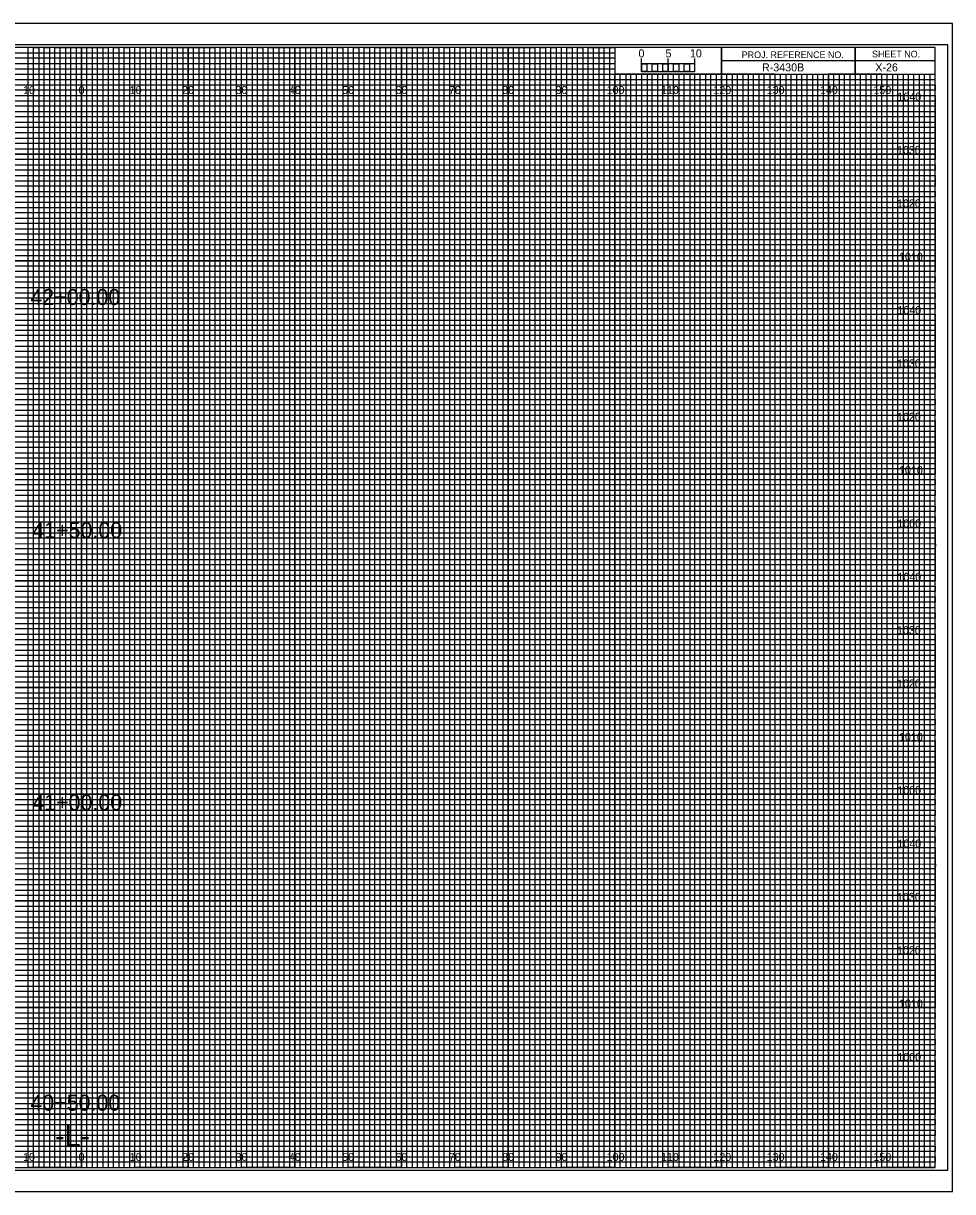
# Model space of a CAD drawing. Extents: x -13 to 323, y 5276 to 5494.
# Drawn here: x 149.1 to 323.3, y 5275.5 to 5494.5 of the extents above; entities that cross this region are included whole.
import ezdxf

# ---------------------------------------------------------------- set-up
doc = ezdxf.new("R2010")
doc.units = 0
for name, color, linetype in [('Prop XS Alignment Label', 7, 'Continuous'), ('Prop XS Bar Scale Labels', 7, 'Continuous'), ('Prop XS Elevation Labels', 7, 'Continuous'), ('Prop XS Offset Labels', 7, 'Continuous'), ('Prop XS Project Number', 7, 'Continuous'), ('Prop XS Sheet Number', 7, 'Continuous'), ('Prop XS Station Labels', 7, 'Continuous'), ('Sheet Cross Section CELL', 7, 'Continuous'), ('Sheet Cross Section Grid Major CELL', 7, 'Continuous'), ('Sheet Cross Section Grid Middle CELL', 7, 'Continuous'), ('Sheet Cross Section Grid Minor 1 CELL', 7, 'Continuous'), ('Sheet Cross Section Grid Minor 2 CELL', 7, 'Continuous'), ('Sheet Cross Section Scale CELL', 7, 'Continuous'), ('Sheet Cutting Line CELL', 7, 'Continuous'), ('Sheet DOT Grid CELL', 7, 'Continuous'), ('Sheet Plot Border Inside CELL', 7, 'Continuous'), ('Sheet Plot Border Outside CELL', 7, 'Continuous')]:
    doc.layers.add(name, color=color, linetype=linetype)

msp = doc.modelspace()

# ---------------------------------------------------------------- linework, layer by layer
at = {"layer": 'Sheet Cross Section CELL'}
for p, q in [((305, 5490), (305, 5485)), ((305, 5485), (305, 5490)), ((280, 5487.5), (280, 5485)), ((320, 5487.49), (280, 5487.49)), ((280, 5485), (320, 5485))]:
    msp.add_line(p, q, dxfattribs=at)
for points in [[(320, 5490), (0, 5490), (0, 5280), (320, 5280)], [(280, 5490), (260, 5490), (260, 5485.03), (280, 5485.03)], [(320, 5490), (280, 5490), (280, 5485), (320, 5485)]]:
    msp.add_lwpolyline(points, close=True, dxfattribs=at)
at = {"layer": 'Sheet Cross Section Grid Major CELL'}
for p, q in [((150, 5490), (140, 5490)), ((150, 5280), (150, 5490)), ((170, 5490), (160, 5490)), ((160, 5490), (160, 5280)), ((170, 5280), (170, 5490)), ((190, 5490), (180, 5490)), ((180, 5490), (180, 5280)), ((190, 5280), (190, 5490)), ((210, 5490), (200, 5490)), ((200, 5490), (200, 5280)), ((210, 5280), (210, 5490)), ((230, 5490), (220, 5490)), ((220, 5490), (220, 5280)), ((230, 5280), (230, 5490)), ((250, 5490), (240, 5490)), ((240, 5490), (240, 5280)), ((250, 5280), (250, 5490)), ((260, 5490), (260, 5280)), ((270, 5280), (270, 5485)), ((290, 5485), (280, 5485)), ((280, 5485), (280, 5280)), ((290, 5280), (290, 5485)), ((310, 5485), (300, 5485)), ((300, 5485), (300, 5280)), ((310, 5280), (310, 5485)), ((160, 5280), (150, 5280)), ((180, 5280), (170, 5280)), ((200, 5280), (190, 5280)), ((220, 5280), (210, 5280)), ((240, 5280), (230, 5280)), ((260, 5280), (250, 5280)), ((280, 5280), (270, 5280)), ((300, 5280), (290, 5280)), ((320, 5280), (310, 5280)), ((320, 5280), (320, 5280))]:
    msp.add_line(p, q, dxfattribs=at)
for points in [[(0, 5480), (320, 5480), (320, 5470), (0, 5470)], [(0, 5460), (320, 5460), (320, 5450), (0, 5450)], [(0, 5440), (320, 5440), (320, 5430), (0, 5430)], [(0, 5420), (320, 5420), (320, 5410), (0, 5410)], [(0, 5400), (320, 5400), (320, 5390), (0, 5390)], [(0, 5380), (320, 5380), (320, 5370), (0, 5370)], [(0, 5360), (320, 5360), (320, 5350), (0, 5350)], [(0, 5340), (320, 5340), (320, 5330), (0, 5330)], [(0, 5320), (320, 5320), (320, 5310), (0, 5310)], [(0, 5300), (320, 5300), (320, 5290), (0, 5290)]]:
    msp.add_lwpolyline(points, dxfattribs=at)
at = {"layer": 'Sheet Cross Section Grid Middle CELL'}
for points in [[(145, 5280), (155, 5280), (155, 5490), (165, 5490), (165, 5280), (175, 5280), (175, 5490), (185, 5490), (185, 5280), (195, 5280), (195, 5490), (205, 5490), (205, 5280), (215, 5280), (215, 5490), (225, 5490), (225, 5280), (235, 5280), (235, 5490), (245, 5490), (245, 5280), (255, 5280), (255, 5490), (259.93, 5490), (260, 5490), (260, 5485), (264.99, 5485), (264.99, 5280), (275, 5280), (275, 5485), (285, 5485), (285, 5280), (295, 5280), (295, 5485), (305, 5485), (305, 5280), (315, 5280), (315, 5485)], [(0, 5485), (275, 5485)], [(0, 5465), (320, 5465), (320, 5475), (0, 5475)], [(0, 5445), (320, 5445), (320, 5455), (0, 5455)], [(0, 5425), (320, 5425), (320, 5435), (0, 5435)], [(0, 5405), (320, 5405), (320, 5415), (0, 5415)], [(0, 5385), (320, 5385), (320, 5395), (0, 5395)], [(0, 5365), (320, 5365), (320, 5375), (0, 5375)], [(0, 5345), (320, 5345), (320, 5355), (0, 5355)], [(0, 5325), (320, 5325), (320, 5335), (0, 5335)], [(0, 5305), (320, 5305), (320, 5315), (0, 5315)], [(0, 5285), (320, 5285), (320, 5295), (0, 5295)]]:
    msp.add_lwpolyline(points, dxfattribs=at)
at = {"layer": 'Sheet Cross Section Grid Minor 1 CELL'}
for p, q in [((0, 5489), (260, 5489)), ((260, 5489), (260, 5487.98)), ((260, 5487.98), (0, 5487.98)), ((0, 5487), (260, 5487)), ((260, 5487), (260, 5485.89)), ((260, 5485.89), (0, 5485.89)), ((0, 5484), (320, 5484))]:
    msp.add_line(p, q, dxfattribs=at)
for points in [[(0, 5483), (270, 5483), (320, 5483), (320, 5482), (0, 5482)], [(0, 5481), (320, 5481), (320, 5479), (0, 5479)], [(0, 5478), (320, 5478), (320, 5477), (0, 5476.98)], [(0, 5476), (320, 5476), (320, 5474), (0, 5474)], [(0, 5473), (320, 5473), (320, 5472), (0, 5472)], [(0, 5471), (320, 5471), (320, 5469), (0, 5469)], [(0, 5468), (320, 5468), (320, 5467), (0, 5467)], [(0, 5466), (320, 5466), (320, 5464), (0, 5464)], [(0, 5463), (320, 5463), (320, 5462), (0, 5462)], [(0, 5461), (320, 5461), (320, 5459), (0, 5459)], [(0, 5458), (320, 5458), (320, 5457), (0, 5457)], [(0, 5456), (320, 5456), (320, 5453.95), (320, 5453), (320, 5452), (0, 5452)], [(0, 5454), (320, 5454), (320, 5453), (0, 5453)], [(0, 5451), (320, 5451), (320, 5449), (0, 5449.03)], [(0, 5449.03), (320, 5449), (320, 5448), (0, 5448)], [(0, 5447), (320, 5447), (320, 5446), (0, 5446)], [(0, 5444), (320, 5444), (320, 5443), (0, 5443)], [(0, 5442), (320, 5442), (320, 5441), (0, 5441)], [(-0.07, 5438.89), (320, 5438.89), (320, 5437.88), (-0.07, 5437.88)], [(0, 5437), (320, 5437), (320, 5436), (0, 5436)], [(0, 5434), (320, 5434), (320, 5433), (0, 5433)], [(0, 5432), (320, 5432), (320, 5431), (0, 5431)], [(0, 5429), (320, 5429), (320, 5428), (0, 5428)], [(0, 5427), (320, 5427), (320, 5426), (0, 5426)], [(0, 5424), (320, 5424), (320, 5423), (0, 5423)], [(0, 5422), (320, 5422), (320, 5421), (0, 5421)], [(0, 5419), (320, 5419), (319.99, 5417.98), (0, 5418)], [(0, 5417), (320, 5417), (320, 5416), (0, 5416)], [(0, 5414), (320, 5414), (320, 5413), (0, 5413)], [(0, 5412), (320, 5412), (320, 5411), (0, 5411)], [(0, 5409), (320, 5409), (320, 5408), (0, 5408)], [(0, 5407), (320, 5407), (320, 5406), (0, 5406)], [(0, 5404), (320, 5404), (320, 5403), (0, 5403)], [(0, 5402), (320, 5402), (320, 5401), (0, 5401)], [(0, 5399), (320, 5399), (320, 5398), (0, 5398)], [(0, 5396.99), (320.07, 5396.91), (320, 5396), (0, 5396)], [(0, 5394), (320, 5394), (320, 5393), (0, 5393)], [(0, 5392), (320, 5392), (320, 5391), (0, 5391)], [(0, 5389), (320, 5389), (320, 5388), (0, 5388)], [(0, 5387), (320, 5387), (320, 5386), (0, 5386)], [(0, 5384), (320, 5384), (320, 5383), (0, 5383)], [(0, 5382), (320, 5382), (320, 5381), (0, 5381)], [(0, 5379), (320, 5379), (320, 5378), (0, 5378)], [(0, 5377), (320, 5377), (320, 5376), (0, 5376)], [(0, 5374), (320, 5374), (320, 5373), (0, 5373)], [(0, 5372), (320, 5372), (320, 5371), (0, 5371)], [(0, 5369), (320, 5369), (320, 5368), (0, 5368)], [(0, 5367), (320, 5367), (320, 5366), (0, 5366)], [(0, 5364), (320, 5364), (320, 5363), (0, 5363)], [(0, 5362), (320, 5362), (320, 5361), (0, 5361)], [(0, 5359), (320, 5359), (319.99, 5357.98), (0, 5358)], [(0, 5357), (320, 5357), (320, 5356), (0, 5356)], [(0, 5354), (320, 5354), (320, 5353), (0, 5353)], [(0, 5352), (320, 5352), (320, 5351), (0, 5351)], [(0, 5349), (320, 5349), (320, 5348), (0, 5348)], [(0, 5347), (320, 5347), (320, 5346), (0, 5346)], [(0, 5344), (320, 5344), (320, 5343), (0, 5343)], [(0, 5342), (320, 5342), (320, 5341), (0, 5341)], [(0, 5339), (320, 5339), (320, 5338), (0, 5338)], [(0, 5336.99), (320.07, 5336.91), (320, 5336), (0, 5336)], [(0, 5334), (320, 5334), (320, 5333), (0, 5333)], [(0, 5332), (320, 5332), (320, 5331), (0, 5331)], [(0, 5329), (320, 5329), (320, 5328), (0, 5328)], [(0, 5327), (320, 5327), (320, 5326), (0, 5326)], [(0, 5324), (320, 5324), (320, 5323), (0, 5323)], [(0, 5322), (320, 5322), (320, 5321), (0, 5321)], [(0, 5319), (320, 5319), (320, 5318), (0, 5318)], [(0, 5317), (320, 5317), (320, 5316), (0, 5316)], [(0, 5314), (320, 5314), (320, 5313), (0, 5313)], [(0, 5312), (320, 5312), (320, 5311), (0, 5311)], [(0, 5309), (320, 5309), (320, 5308), (0, 5308)], [(0, 5307), (320, 5307), (320, 5306), (0, 5306)], [(0, 5304), (320, 5304), (320, 5303), (0, 5303)], [(0, 5302), (320, 5302), (320, 5301), (0, 5301)], [(0, 5299), (320, 5299), (320, 5298), (0, 5298)], [(0, 5297), (320, 5297), (320, 5296), (0, 5296)], [(0, 5294), (320, 5294), (320, 5293), (0, 5293)], [(0, 5292), (320, 5292), (320, 5291), (0, 5291)], [(0, 5289), (320, 5289), (320, 5288), (0, 5288)], [(0, 5287), (320, 5287), (320, 5286), (0, 5286)], [(0, 5284), (320, 5284), (320, 5283), (0, 5283)], [(0, 5282), (320, 5282), (320, 5281), (0, 5281)]]:
    msp.add_lwpolyline(points, dxfattribs=at)
at = {"layer": 'Sheet Cross Section Grid Minor 2 CELL'}
for p, q in [((267, 5485), (266.01, 5485)), ((266.01, 5485), (266.01, 5280)), ((267, 5280), (267, 5485)), ((269, 5485), (268, 5485)), ((268, 5485), (268, 5280)), ((269, 5280), (269, 5485)), ((266.01, 5280), (265, 5280)), ((268, 5280), (267, 5280))]:
    msp.add_line(p, q, dxfattribs=at)
for points in [[(150, 5280), (151, 5280), (151, 5490), (152, 5490), (152, 5280)], [(152, 5280), (153, 5280), (153, 5490), (154, 5490), (154, 5280)], [(155, 5280), (156, 5280), (156, 5490), (157, 5490), (157, 5280)], [(157, 5280), (158, 5280), (158, 5490), (159, 5490), (159, 5280)], [(160, 5280), (161, 5280), (161, 5490), (162, 5490), (162, 5280)], [(162, 5280), (163, 5280), (163, 5490), (164, 5490), (164, 5280)], [(165, 5280), (166, 5280), (166, 5490), (167, 5490), (167, 5280)], [(167, 5280), (168, 5280), (168, 5490), (169, 5490), (169, 5280)], [(170, 5280), (171, 5280), (171, 5490), (172, 5490), (172, 5280)], [(172, 5280), (173, 5280), (173, 5490), (174, 5490), (174, 5280)], [(175, 5280), (176, 5280), (176, 5490), (177, 5490), (177, 5280)], [(177, 5280), (178, 5280), (178, 5490), (179, 5490), (179, 5280)], [(180, 5280), (181, 5280), (181, 5490), (182, 5490), (182, 5280)], [(182, 5280), (183, 5280), (183, 5490), (184, 5490), (184, 5280)], [(185, 5280), (186, 5280), (186, 5490), (187, 5490), (187, 5280)], [(187, 5280), (188, 5280), (188, 5490), (189, 5490), (189, 5280)], [(190, 5280), (191, 5280), (191, 5490), (192, 5490), (192, 5280)], [(192, 5280), (193, 5280), (193, 5490), (194, 5490), (194, 5280)], [(195, 5280), (196, 5280), (196, 5490), (197, 5490), (197, 5280)], [(197, 5280), (198, 5280), (198, 5490), (199, 5490), (199, 5280)], [(200, 5280), (201, 5280), (201, 5490), (202, 5490), (202, 5280)], [(202, 5280), (203, 5280), (203, 5490), (204, 5490), (204, 5280)], [(205, 5280), (206, 5280), (206, 5490), (207, 5490), (207, 5280)], [(207, 5280), (208, 5280), (208, 5490), (209, 5490), (209, 5280)], [(210, 5280), (211, 5280), (211, 5490), (212, 5490), (212, 5280)], [(212, 5280), (213, 5280), (213, 5490), (214, 5490), (214, 5280)], [(215, 5280), (216, 5280), (216, 5490), (217, 5490), (217, 5280)], [(217, 5280), (218, 5280), (218, 5490), (219, 5490), (219, 5280)], [(220, 5280), (221, 5280), (221, 5490), (222, 5490), (222, 5280)], [(222, 5280), (223, 5280), (223, 5490), (224, 5490), (224, 5280)], [(225, 5280), (226, 5280), (226, 5490), (227, 5490), (227, 5280)], [(227, 5280), (228, 5280), (228, 5490), (229, 5490), (229, 5280)], [(230, 5280), (231, 5280), (231, 5490), (232, 5490), (232, 5280)], [(232, 5280), (233, 5280), (233, 5490), (234, 5490), (234, 5280)], [(235, 5280), (236, 5280), (236, 5490), (237, 5490), (237, 5280)], [(237, 5280), (238, 5280), (238, 5490), (239, 5490), (239, 5280)], [(240, 5280), (241, 5280), (241, 5490), (242, 5490), (242, 5280)], [(242, 5280), (243, 5280), (243, 5490), (244, 5490), (244, 5280)], [(245, 5280), (246, 5280), (246, 5490), (247, 5490), (247, 5280)], [(247, 5280), (248, 5280), (248, 5490), (249, 5490), (249, 5280)], [(250, 5280), (251, 5280), (251, 5490), (252, 5490), (252, 5280)], [(252, 5280), (253, 5280), (253, 5490), (254, 5490), (254, 5280)], [(255, 5280), (256, 5280), (256, 5490), (257, 5490), (257, 5280)], [(257, 5280), (258, 5280), (258, 5490), (259, 5490), (259, 5280)], [(260, 5280), (261, 5280), (261, 5485), (262.02, 5485), (262.02, 5280)], [(262, 5280), (263, 5280), (263, 5485), (263.99, 5485), (263.99, 5280)], [(270, 5280), (270.98, 5280), (270.98, 5485), (272, 5485), (272, 5280)], [(272, 5280), (273, 5280), (273, 5485), (274.05, 5485), (274.05, 5280)], [(275, 5280), (276, 5280), (276, 5485), (277, 5485), (277, 5280)], [(277, 5280), (278, 5280), (278, 5485), (279, 5485), (279, 5280)], [(280, 5280), (281, 5280), (281, 5485), (282, 5485), (282, 5280)], [(282, 5280), (283, 5280), (283, 5485), (284, 5485), (284, 5280)], [(285, 5280), (286, 5280), (286, 5485), (287, 5485), (287, 5280)], [(287, 5280), (288, 5280), (288, 5485), (289, 5485), (289, 5280)], [(290, 5280), (291, 5280), (291, 5485), (292, 5485), (292, 5280)], [(292, 5280), (293, 5280), (293, 5485), (294, 5485), (294, 5280)], [(295, 5280), (296, 5280), (296, 5485), (297, 5485), (297, 5280)], [(297, 5280), (298, 5280), (298, 5485), (299, 5485), (299, 5280)], [(300, 5280), (301, 5280), (301, 5485), (302, 5485), (302, 5280)], [(302, 5280), (303, 5280), (303, 5485), (304, 5485), (304, 5280)], [(305, 5280), (306, 5280), (306, 5485), (307, 5485), (307, 5280)], [(307, 5280), (308, 5280), (308, 5485), (309, 5485), (309, 5280)], [(310, 5280), (311, 5280), (311, 5485), (312, 5485), (312, 5280)], [(312, 5280), (313, 5280), (313, 5485), (314, 5485), (314, 5280)], [(315, 5280), (316, 5280), (316, 5485), (317, 5485), (317, 5280)], [(317, 5280), (318, 5280), (318, 5485), (319, 5485), (319, 5280)]]:
    msp.add_lwpolyline(points, dxfattribs=at)
at = {"layer": 'Sheet Cross Section Scale CELL'}
for p, q in [((265, 5485.49), (265, 5487.9)), ((265, 5486.9), (265, 5487.9)), ((270, 5485.49), (270, 5487.9)), ((275, 5485.49), (275, 5487.9)), ((275, 5486.9), (275, 5487.9))]:
    msp.add_line(p, q, dxfattribs=at)
for points in [[(275, 5486.9), (265, 5486.9), (265, 5485.49), (275, 5485.49)], [(265, 5486.9), (266, 5486.9), (266, 5485.49), (265, 5485.49)], [(267, 5486.9), (268, 5486.9), (268, 5485.49), (267, 5485.49)], [(269, 5486.9), (270, 5486.9), (270, 5485.49), (269, 5485.49)], [(271, 5486.9), (272, 5486.9), (272, 5485.49), (271, 5485.49)], [(273, 5486.9), (274, 5486.9), (274, 5485.49), (273, 5485.49)]]:
    msp.add_lwpolyline(points, close=True, dxfattribs=at)
at = {"layer": 'Sheet Cutting Line CELL'}
for p, q in [((323.3, 5494.5), (-13.4, 5494.5)), ((-13.4, 5275.5), (323.3, 5275.5))]:
    msp.add_line(p, q, dxfattribs=at)
at = {"layer": 'Sheet DOT Grid CELL'}
for p, q in [((150, 5280), (150, 5490)), ((160, 5280), (160, 5490)), ((170, 5280), (170, 5490)), ((180, 5280), (180, 5490)), ((190, 5280), (190, 5490)), ((200, 5280), (200, 5490)), ((210, 5280), (210, 5490)), ((220, 5280), (220, 5490)), ((230, 5280), (230, 5490)), ((240, 5280), (240, 5490)), ((250, 5280), (250, 5490)), ((260, 5280), (260, 5484.69)), ((270, 5280), (270, 5484.69)), ((280, 5280), (280, 5484.69)), ((290, 5280), (290, 5484.69)), ((300, 5280), (300, 5484.69)), ((310, 5280), (310, 5484.69)), ((0, 5480), (320, 5480)), ((0, 5470), (320, 5470)), ((0, 5460), (320, 5460)), ((0, 5450), (320, 5450)), ((0, 5440), (320, 5440)), ((0, 5430), (320, 5430)), ((0, 5420), (320, 5420)), ((0, 5410), (320, 5410)), ((0, 5400), (320, 5400)), ((0, 5390), (320, 5390)), ((0, 5380), (320, 5380)), ((0, 5370), (320, 5370)), ((0, 5360), (320, 5360)), ((0, 5350), (320, 5350)), ((0, 5340), (320, 5340)), ((0, 5330), (320, 5330)), ((0, 5320), (320, 5320)), ((0, 5310), (320, 5310)), ((0, 5300), (320, 5300)), ((0, 5290), (320, 5290))]:
    msp.add_line(p, q, dxfattribs=at)
at = {"layer": 'Sheet Plot Border Inside CELL'}
msp.add_lwpolyline([(-10.8, 5279.5), (322.4, 5279.5), (322.4, 5490.5), (-10.8, 5490.5)], close=True, dxfattribs=at)
at = {"layer": 'Sheet Plot Border Outside CELL'}
msp.add_lwpolyline([(-13.4, 5275.5), (323.3, 5275.5), (323.3, 5494.5), (-13.4, 5494.5)], close=True, dxfattribs=at)

# ---------------------------------------------------------------- texts
at = {"layer": 'Prop XS Alignment Label'}
msp.add_text('-L-', height=4, dxfattribs=at).set_placement((155.06, 5284))
at = {"layer": 'Prop XS Bar Scale Labels'}
for s, p in [('5', (269.47, 5488.12)), ('10', (274.04, 5488.12))]:
    msp.add_text(s, height=1.5, dxfattribs=at).set_placement(p)
at = {"layer": 'Prop XS Elevation Labels'}
for s, p in [('1040', (312.95, 5480)), ('1030', (312.86, 5470)), ('1020', (312.87, 5460)), ('1010', (313.25, 5450)), ('1040', (312.95, 5440)), ('1030', (312.86, 5430)), ('1020', (312.87, 5420)), ('1010', (313.25, 5410)), ('1000', (312.92, 5400)), ('1040', (312.95, 5390)), ('1030', (312.86, 5380)), ('1020', (312.87, 5370)), ('1010', (313.25, 5360)), ('1000', (312.92, 5350)), ('1040', (312.95, 5340)), ('1030', (312.86, 5330)), ('1020', (312.87, 5320)), ('1010', (313.25, 5310)), ('1000', (312.92, 5300))]:
    msp.add_text(s, height=1.5, dxfattribs=at).set_placement(p)
at = {"layer": 'Prop XS Offset Labels'}
for s, p in [('10', (149.04, 5481.25)), ('0', (159.45, 5481.25)), ('0', (159.45, 5481.25)), ('10', (169.04, 5481.25)), ('20', (178.86, 5481.25)), ('30', (188.86, 5481.25)), ('40', (198.86, 5481.25)), ('50', (208.86, 5481.25)), ('60', (218.86, 5481.25)), ('70', (228.86, 5481.25)), ('80', (238.86, 5481.25)), ('90', (248.86, 5481.25)), ('100', (258.44, 5481.25)), ('110', (268.62, 5481.25)), ('120', (278.44, 5481.25)), ('130', (288.44, 5481.25)), ('140', (298.44, 5481.25)), ('150', (308.44, 5481.25)), ('10', (149.04, 5281.25)), ('0', (159.45, 5281.25)), ('0', (159.45, 5281.25)), ('10', (169.04, 5281.25)), ('20', (178.86, 5281.25)), ('30', (188.86, 5281.25)), ('40', (198.86, 5281.25)), ('50', (208.86, 5281.25)), ('60', (218.86, 5281.25)), ('70', (228.86, 5281.25)), ('80', (238.86, 5281.25)), ('90', (248.86, 5281.25)), ('100', (258.44, 5281.25)), ('110', (268.62, 5281.25)), ('120', (278.44, 5281.25)), ('130', (288.44, 5281.25)), ('140', (298.44, 5281.25)), ('150', (308.44, 5281.25))]:
    msp.add_text(s, height=1.5, dxfattribs=at).set_placement(p)
at = {"layer": 'Prop XS Project Number'}
msp.add_text('R-3430B', height=1.5, dxfattribs=at).set_placement((287.56, 5485.5))
at = {"layer": 'Prop XS Sheet Number'}
msp.add_text('X-26', height=1.5, dxfattribs=at).set_placement((308.8, 5485.5))
at = {"layer": 'Prop XS Station Labels'}
for s, p in [('42+00.00', (150.41, 5441.7)), ('41+50.00', (150.77, 5398)), ('41+00.00', (150.77, 5346.97)), ('40+50.00', (150.41, 5290.67))]:
    msp.add_text(s, height=3, dxfattribs=at).set_placement(p)
at = {"layer": 'Sheet Cross Section CELL'}
for s, p in [('PROJ. REFERENCE NO.', (283.77, 5487.99)), ('SHEET NO.', (308.19, 5488.12))]:
    msp.add_text(s, height=1.25, dxfattribs=at).set_placement(p)
at = {"layer": 'Sheet Cross Section Scale CELL'}
msp.add_text('0', height=1.5, dxfattribs=at).set_placement((264.41, 5488.12))

doc.saveas('drawing.dxf')
